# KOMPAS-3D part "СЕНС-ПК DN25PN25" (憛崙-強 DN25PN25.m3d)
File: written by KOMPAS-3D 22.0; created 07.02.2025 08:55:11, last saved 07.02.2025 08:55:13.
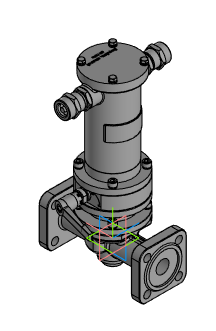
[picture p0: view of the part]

Document properties: Автор: setup; Полное имя файла: \\10.10.77.77\!! users\Савин А.Г\!Клапаны 3D для заказчика\СЕНС-ПК\1. СЕНС-ПК\СЕНС-ПК DN25PN25.m3d

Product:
- Body: Тело 3
    Масса: 10.63044
- Part/product: СЕНС-ПК DN25PN25
    Масса: 10.456296

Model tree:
1. Операция без истории:1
